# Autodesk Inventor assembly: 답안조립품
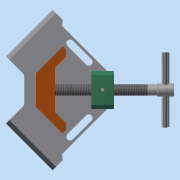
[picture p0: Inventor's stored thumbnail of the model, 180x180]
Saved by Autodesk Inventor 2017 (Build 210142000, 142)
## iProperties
Part Number: 답안조립품
Material: 일반
Document SubType Name: Assembly
Designer: mrc
Author: mrc
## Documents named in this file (11)
- C:\Users\mrc\Desktop\700506V1055\답안조립품.iam
- C:\Users\mrc\Desktop\700506V1055\본체.ipt
- C:\Users\mrc\Desktop\700506V1055\리드스크류.ipt
- C:\Users\mrc\Desktop\700506V1055\멈춤나사 M4x5.ipt
- C:\Users\mrc\Desktop\700506V1055\멈춤나사 M4x10.ipt
- C:\Users\mrc\Desktop\700506V1055\볼트 M4x16.ipt
- C:\Users\mrc\Desktop\700506V1055\부시.ipt
- C:\Users\mrc\Desktop\700506V1055\서포트.ipt
- C:\Users\mrc\Desktop\700506V1055\조.ipt
- C:\Users\mrc\Desktop\700506V1055\평행 핀 2.5x24.ipt
- C:\Users\mrc\Desktop\700506V1055\핸들.ipt
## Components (1 placed, 1 different names)
1. 핸들:1
